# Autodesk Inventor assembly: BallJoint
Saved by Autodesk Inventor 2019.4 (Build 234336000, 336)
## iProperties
Created: 2020-02
Part Number: BallJoint
Document SubType Name: Assembly
Designer: Administrator
Title: BallJoint v14
Author: Administrator
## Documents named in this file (3)
- c:\worker\convert-fusion-r01\tmp\job-1\5\output\files\e4333473-a38b-4431-9958-ad24a2f67704\BallJoint v14.iam
- c:\worker\convert-fusion-r01\tmp\job-1\5\output\files\e4333473-a38b-4431-9958-ad24a2f67704\Component1_1.ipt
- c:\worker\convert-fusion-r01\tmp\job-1\5\output\files\e4333473-a38b-4431-9958-ad24a2f67704\Component2_1.ipt
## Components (2 placed, 2 different names)
1. Component1:1
2. Component2:1
